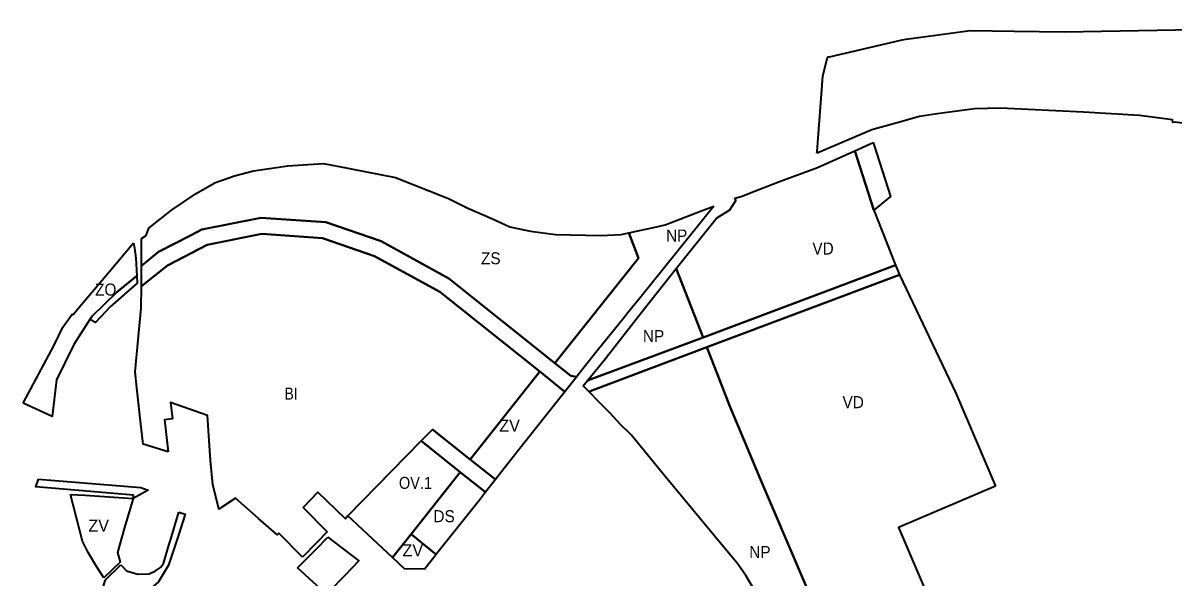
# Model space of a CAD drawing. Extents: x -650971 to -642489, y -1074311 to -1062745.
# Drawn here: x -650112 to -648968, y -1069716 to -1069164 of the extents above; entities that cross this region are included whole.
import ezdxf

# ---------------------------------------------------------------- set-up
doc = ezdxf.new("R2010")
doc.units = 0
doc.header["$LTSCALE"] = 4.8
for name, color, linetype, lineweight in [('11', 7, 'Continuous', 35), ('15', 7, 'Continuous', 35), ('2', 7, 'Continuous', 35), ('24', 7, 'Continuous', 35), ('35', 7, 'Continuous', 35), ('40', 7, 'Continuous', 35), ('41', 7, 'Continuous', 35), ('42', 7, 'Continuous', 35), ('48', 7, 'Continuous', 35), ('62', 7, 'Continuous', 35)]:
    doc.layers.add(name, color=color, linetype=linetype, lineweight=lineweight)

msp = doc.modelspace()

# ---------------------------------------------------------------- linework, layer by layer
at = {"layer": '11'}
msp.add_lwpolyline([(-649788.91, -1069654.4), (-649715.908, -1069579.804), (-649677.124, -1069610.681), (-649726.033, -1069672.415), (-649744.517, -1069695.746)], close=True, dxfattribs=at)
at = {"layer": '15'}
for points in [[(-649994.329, -1069405.451), (-649977.239, -1069391.714), (-649945.397, -1069375.277), (-649934.363, -1069369.537), (-649875.434, -1069357.751), (-649810.846, -1069362.154), (-649755.971, -1069381.179), (-649688.625, -1069418.156), (-649582.972, -1069502.334)], [(-649598.004, -1069510.814), (-649697.525, -1069431.522), (-649762.488, -1069395.854), (-649814.067, -1069377.972), (-649874.391, -1069373.859), (-649929.015, -1069384.784), (-649968.465, -1069405.189), (-649994.293, -1069425.949), (-649994.329, -1069405.451)], [(-649550.53, -1069519.68), (-649435.578, -1069476.772), (-649244.08, -1069404.753), (-649240.202, -1069414.528), (-649431.761, -1069486.57)], [(-650045.72, -1069459.1), (-650043.521, -1069455.69), (-650018.873, -1069431.749), (-649999.01, -1069415.628), (-649998.512, -1069422.926)], [(-649998.512, -1069422.926), (-650025.31, -1069446.49), (-650040.012, -1069461.999), (-650045.72, -1069459.1)], [(-649431.761, -1069486.57), (-649547.733, -1069530.185), (-649548.881, -1069530.963)], [(-649582.972, -1069502.334), (-649566.951, -1069515.099), (-649561.17, -1069515.83)], [(-649561.17, -1069515.83), (-649561.91, -1069516.78), (-649572.972, -1069530.758), (-649598.004, -1069510.814)], [(-649548.881, -1069530.963), (-649549.69, -1069530.14), (-649551.32, -1069528.49), (-649554.83, -1069525), (-649550.53, -1069519.68)], [(-650002.65, -1069637.14), (-650002.39, -1069633.65), (-650099.55, -1069625.53), (-650096.627, -1069617.746)], [(-650096.627, -1069617.746), (-649994.913, -1069626.246), (-649987.49, -1069628.6), (-650002.65, -1069637.14)]]:
    msp.add_lwpolyline(points, dxfattribs=at)
msp.add_lwpolyline([(-649715.908, -1069579.804), (-649704.646, -1069568.296), (-649667.188, -1069598.14), (-649641.978, -1069618.226), (-649651.846, -1069630.82), (-649677.124, -1069610.681)], close=True, dxfattribs=at)
at = {"layer": '2'}
for points in [[(-649994.293, -1069425.949), (-649968.465, -1069405.189), (-649929.015, -1069384.784), (-649874.391, -1069373.859), (-649814.067, -1069377.972), (-649762.488, -1069395.854), (-649697.525, -1069431.522), (-649598.004, -1069510.814), (-649667.188, -1069598.14)], [(-650000.59, -1069511.15), (-649994.53, -1069447.61), (-649994.293, -1069425.949)], [(-649967.81, -1069590.74), (-649992.589, -1069582.88), (-649994.794, -1069563.119), (-649998.5, -1069529.88), (-649998.81, -1069527.07), (-650000.59, -1069511.15)], [(-649833.941, -1069695.24), (-649857.49, -1069671.46), (-649859.17, -1069673.22), (-649859.96, -1069672.53), (-649877.82, -1069656.83), (-649900.64, -1069636.78), (-649917.38, -1069647.56), (-649918.35, -1069643.45), (-649923.17, -1069623.14), (-649925.53, -1069599.38), (-649928.48, -1069554.57), (-649965.26, -1069541.51), (-649963.43, -1069557.91)], [(-649963.43, -1069557.91), (-649971.38, -1069558.79), (-649967.81, -1069590.74)], [(-649667.188, -1069598.14), (-649704.646, -1069568.296), (-649715.908, -1069579.804), (-649788.91, -1069654.4)], [(-649788.91, -1069654.4), (-649791.3, -1069657.21), (-649818.71, -1069630.64), (-649833.38, -1069646.08), (-649809.47, -1069670.13)], [(-649809.47, -1069670.13), (-649819.98, -1069680.92), (-649833.941, -1069695.24)], [(-649838.99, -1069706.15), (-649820.64, -1069687.33), (-649808.96, -1069675.34)], [(-649808.96, -1069675.34), (-649777.94, -1069699.2), (-649792.13, -1069713.65), (-649807.66, -1069729.46), (-649810.41, -1069732.28), (-649819.9, -1069723.61), (-649838.99, -1069706.15)]]:
    msp.add_lwpolyline(points, dxfattribs=at)
at = {"layer": '24'}
msp.add_line((-649284.695, -1069291.033), (-649266.331, -1069282.804), dxfattribs=at)
for points in [[(-649125.864, -1069172.018), (-649076.02, -1069172.683), (-648781.015, -1069167.44), (-648711.546, -1069164.545), (-648698.04, -1069163.983)], [(-649309.726, -1069197.515), (-649237.512, -1069180.731), (-649233.797, -1069180.221), (-649233.504, -1069180.181)], [(-649233.504, -1069180.181), (-649169.781, -1069171.432), (-649125.864, -1069172.018)], [(-649322.22, -1069293.54), (-649322.09, -1069291.73), (-649316.47, -1069216.91), (-649311.633, -1069197.958), (-649310.915, -1069197.791), (-649309.726, -1069197.515)], [(-648918.889, -1069268.875), (-648924.13, -1069268.21), (-648937.91, -1069266.51), (-648965.8, -1069262.75), (-648968.05, -1069263.06), (-648968.49, -1069260.36), (-649001.3, -1069255.92), (-649056.95, -1069252.55), (-649139.63, -1069248.73), (-649165.62, -1069249.43), (-649202.63, -1069254.4), (-649220.18, -1069257.03), (-649242.5, -1069263.3), (-649267.5, -1069270.41), (-649319.72, -1069292.47), (-649322.22, -1069293.54)], [(-649266.331, -1069282.804), (-649265.331, -1069285.923), (-649249.069, -1069336.66), (-649265.774, -1069350.068), (-649284.695, -1069291.033)], [(-649726.033, -1069672.415), (-649677.124, -1069610.681), (-649651.846, -1069630.82)], [(-649651.846, -1069630.82), (-649658.13, -1069638.84), (-649700.42, -1069691.8), (-649701.211, -1069692.826), (-649726.033, -1069672.415)]]:
    msp.add_lwpolyline(points, dxfattribs=at)
at = {"layer": '35'}
msp.add_line((-649431.761, -1069486.57), (-649240.202, -1069414.528), dxfattribs=at)
for points in [[(-649403.92, -1069338.26), (-649396.52, -1069336.09), (-649389.4, -1069333.35), (-649359.48, -1069321.82), (-649324.3, -1069308.59), (-649321.69, -1069307.61), (-649284.695, -1069291.033), (-649265.774, -1069350.068), (-649244.08, -1069404.753), (-649435.578, -1069476.772), (-649462.25, -1069408.32)], [(-649462.25, -1069408.32), (-649422.19, -1069357.99), (-649408.81, -1069349.89), (-649403.03, -1069340.66), (-649403.92, -1069338.26)], [(-649240.202, -1069414.528), (-649184.1, -1069532.2), (-649144.57, -1069624.6)], [(-649246.81, -1069926.27), (-649312.03, -1069773.33), (-649364.44, -1069650.55), (-649379.32, -1069615.71), (-649388.438, -1069594.296), (-649409.349, -1069544.532), (-649416.52, -1069525.68), (-649431.761, -1069486.57)], [(-649144.57, -1069624.6), (-649241.11, -1069665.9), (-649202.99, -1069754.99), (-649200.64, -1069756.53), (-649184.05, -1069768.45), (-649154.76, -1069792.11), (-649085.41, -1069762.44)]]:
    msp.add_lwpolyline(points, dxfattribs=at)
at = {"layer": '40'}
for points in [[(-649667.188, -1069598.14), (-649598.004, -1069510.814), (-649572.972, -1069530.758)], [(-649572.972, -1069530.758), (-649620.45, -1069590.75), (-649641.978, -1069618.226), (-649667.188, -1069598.14)], [(-650064.77, -1069633.06), (-650050.26, -1069633.65), (-650002.65, -1069637.14)], [(-650031.64, -1069715.9), (-650039.11, -1069704.76), (-650047.45, -1069690.69), (-650052.88, -1069679.49), (-650064.77, -1069633.06)], [(-650002.65, -1069637.14), (-650011.15, -1069665.82), (-650018.31, -1069690.89), (-650015.53, -1069700.21), (-650031.64, -1069715.9)], [(-649957.15, -1069650.76), (-649950.69, -1069652.54), (-649957.54, -1069673.5), (-649958.87, -1069677.59), (-649967.27, -1069703.29), (-649977.31, -1069720.05), (-650006.85, -1069745.3), (-650032.13, -1069723.75), (-650030.26, -1069717.96), (-650014.74, -1069702.9)], [(-650014.74, -1069702.9), (-650009.29, -1069708.92), (-649998, -1069712.26), (-649986.69, -1069712.03), (-649980.22, -1069709.07), (-649975.45, -1069705.65), (-649972.35, -1069701.78), (-649966.59, -1069682.44), (-649965.45, -1069678.6), (-649957.15, -1069650.76)], [(-649744.517, -1069695.746), (-649726.033, -1069672.415), (-649701.211, -1069692.826)], [(-649701.211, -1069692.826), (-649710.589, -1069704.99), (-649712.64, -1069707.43), (-649732.52, -1069706.92), (-649744.517, -1069695.746)]]:
    msp.add_lwpolyline(points, dxfattribs=at)
at = {"layer": '41'}
for points in [[(-649994.38, -1069378.33), (-649989.67, -1069375.36), (-649987.12, -1069368.03), (-649964.53, -1069350.02), (-649939.81, -1069333.47), (-649922.11, -1069323.35), (-649921.54, -1069323.03), (-649901.58, -1069316.01), (-649882.93, -1069311.1), (-649848.62, -1069305.95), (-649813.3, -1069303.66), (-649789, -1069308.31), (-649785.8, -1069308.94), (-649741.5, -1069317.74), (-649690.59, -1069337.98), (-649688.73, -1069338.7), (-649670.23, -1069347.9), (-649645.03, -1069358.8), (-649627.76, -1069366.8), (-649607.18, -1069370.92), (-649582.25, -1069374.51), (-649537.32, -1069375.23), (-649517.17, -1069374.3), (-649509.42, -1069372.61)], [(-649582.972, -1069502.334), (-649688.625, -1069418.156), (-649755.971, -1069381.179), (-649810.846, -1069362.154), (-649875.434, -1069357.751), (-649934.363, -1069369.537), (-649945.397, -1069375.277), (-649977.239, -1069391.714), (-649994.329, -1069405.451)], [(-649509.42, -1069372.61), (-649499.761, -1069397.905), (-649582.972, -1069502.334)], [(-649994.329, -1069405.451), (-649994.34, -1069398.8), (-649994.35, -1069394.43), (-649994.38, -1069378.33)]]:
    msp.add_lwpolyline(points, dxfattribs=at)
at = {"layer": '42'}
for points in [[(-650112.18, -1069542.11), (-650081.29, -1069484.35), (-650072.5, -1069466.44), (-650063.12, -1069453.54), (-650062.17, -1069454.05), (-650060.29, -1069451.7), (-650057.49, -1069448.18), (-650026.33, -1069411.47), (-650003.73, -1069384.71), (-650002.11, -1069382.8)], [(-650002.11, -1069382.8), (-650001.13, -1069388.13), (-649999.95, -1069397.98), (-649999.01, -1069415.628)], [(-649999.01, -1069415.628), (-650018.873, -1069431.749), (-650043.521, -1069455.69), (-650045.72, -1069459.1)], [(-650045.72, -1069459.1), (-650061.51, -1069483.79), (-650079, -1069518.93), (-650083.1, -1069555.34), (-650112.18, -1069542.11)]]:
    msp.add_lwpolyline(points, dxfattribs=at)
at = {"layer": '48'}
for points in [[(-649424.8, -1069346.14), (-649498.47, -1069437.65), (-649510.56, -1069452.67), (-649513.66, -1069456.53), (-649540.81, -1069490.25), (-649555.16, -1069508.07), (-649556.9, -1069510.24), (-649558.71, -1069512.62), (-649560.54, -1069515.02), (-649561.17, -1069515.83)], [(-649509.42, -1069372.61), (-649481.92, -1069366.62), (-649473.35, -1069364.76), (-649438.17, -1069351.27), (-649424.8, -1069346.14)], [(-649582.972, -1069502.334), (-649499.761, -1069397.905), (-649509.42, -1069372.61)], [(-649548.881, -1069530.963), (-649547.733, -1069530.185), (-649431.761, -1069486.57)], [(-649431.761, -1069486.57), (-649416.52, -1069525.68), (-649409.349, -1069544.532), (-649388.438, -1069594.296), (-649379.32, -1069615.71), (-649364.44, -1069650.55), (-649312.03, -1069773.33), (-649246.81, -1069926.27)], [(-649561.17, -1069515.83), (-649566.951, -1069515.099), (-649582.972, -1069502.334)], [(-649372.56, -1069802.33), (-649370.94, -1069787.45), (-649372.2, -1069772.58), (-649376.01, -1069754.58), (-649379.49, -1069740.04), (-649385.25, -1069726.48), (-649392.85, -1069713.53), (-649401.77, -1069701.47), (-649415.12, -1069685.26), (-649474.46, -1069613.59), (-649507.23, -1069573.85), (-649517.81, -1069563.27), (-649527.84, -1069552.16), (-649538.49, -1069541.54), (-649548.881, -1069530.963)]]:
    msp.add_lwpolyline(points, dxfattribs=at)
msp.add_lwpolyline([(-649550.53, -1069519.68), (-649534.06, -1069499.33), (-649493.94, -1069448.14), (-649462.25, -1069408.32), (-649435.578, -1069476.772)], close=True, dxfattribs=at)

# ---------------------------------------------------------------- texts
at = {"layer": '62'}
for s, width, p in [('NP', 0.95, (-649472.389, -1069381.42)), ('VD', 0.95, (-649326.761, -1069394.352)), ('ZS', 0.95, (-649656.482, -1069404.05)), ('ZO', 0.95, (-650040.423, -1069435.188)), ('NP', 0.95, (-649495.389, -1069481.42)), ('BI', 0.85, (-649851.88, -1069538.658)), ('VD', 0.95, (-649296.767, -1069547.204)), ('OV.1', 0.9, (-649738.147, -1069627.487)), ('DS', 0.95, (-649703.778, -1069660.629)), ('NP', 0.95, (-649389.556, -1069696.287))]:
    msp.add_text(s, height=12, dxfattribs=dict(at, width=width)).set_placement(p)
for p in [(-649638.283, -1069570.48), (-650047.124, -1069669.988), (-649734.572, -1069694.498)]:
    msp.add_text('ZV', height=12, dxfattribs=at).set_placement(p)

doc.saveas('drawing.dxf')
